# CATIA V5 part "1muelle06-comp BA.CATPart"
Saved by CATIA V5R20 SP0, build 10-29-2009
Part number: 1muelle06-comp BA
Revision: ANY
Definition: UNKNOWN
Nomenclature: 1muelle06-comp BA
Source: Unknown
Bounding box of the stored display mesh (mm): x -4.9 to 4.9, y -4.9 to 4.9, z -0.001 to 8.249
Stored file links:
  C:\Users\Utente\Desktop\IO LAVORO\3D X SITO CF\CUMSA\3D files BA\BA 061418\1muelle06-comp BA.CATPart
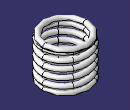
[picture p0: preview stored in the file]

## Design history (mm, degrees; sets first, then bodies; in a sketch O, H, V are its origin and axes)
Set1 "FacciaKO#NONE#518"
  DatumSurface1 "Sup518_1"
  DatumCurve1 "Crv518_1"
Set2 "FacciaKO#NONE#510"
  DatumSurface2 "Sup510_1"
  DatumCurve2 "Crv510_1"
Body1 "Cortar-Extruir1" (main body)
  Solid1: solid without history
